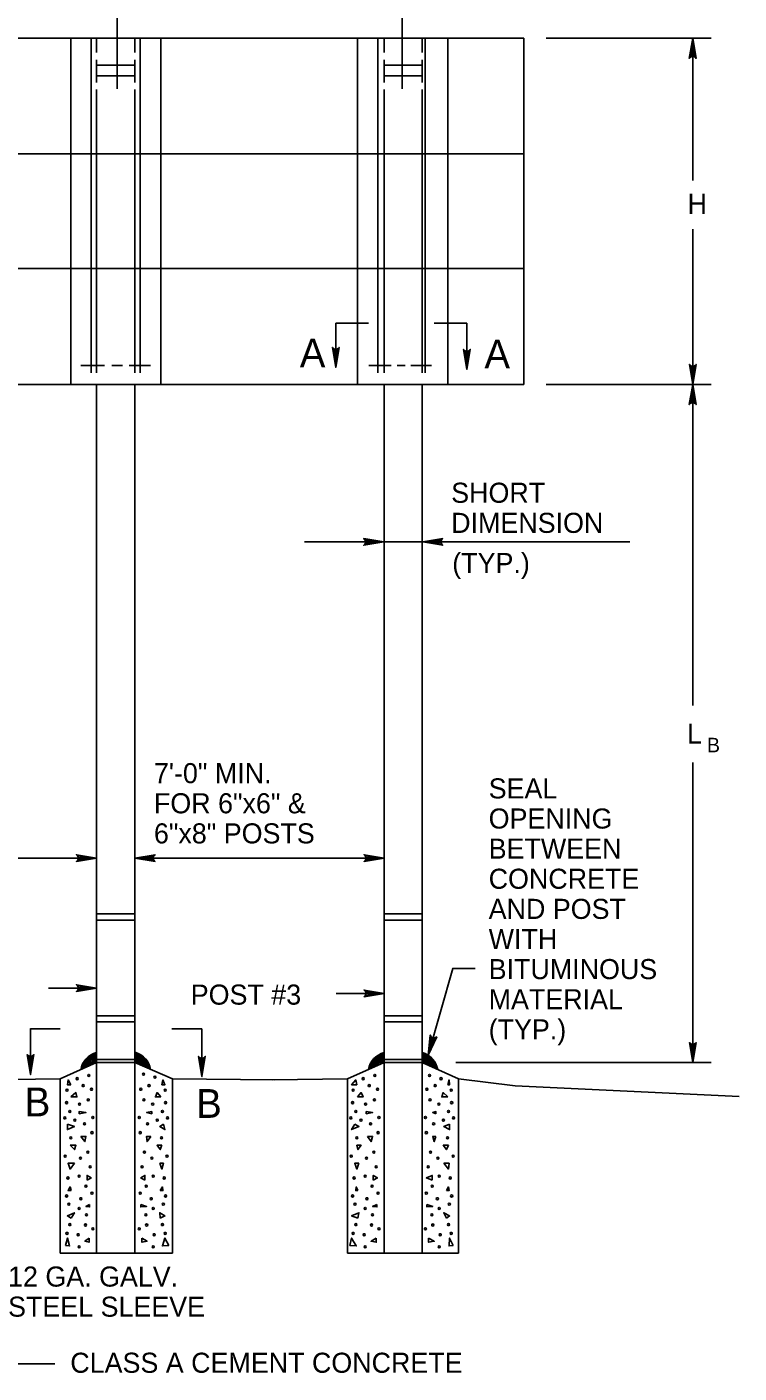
# Model space of a CAD drawing. Extents: x -2340 to 628, y -879 to 309.
# Drawn here: x 247.1 to 353.5, y 1.8 to 203 of the extents above; entities that cross this region are included whole.
import ezdxf

# ---------------------------------------------------------------- set-up
doc = ezdxf.new("R2010")
doc.units = 0
for name, color, linetype in [('Level 2', 7, 'Continuous'), ('Level 3', 7, 'Continuous'), ('Level 4', 7, 'Continuous')]:
    doc.layers.add(name, color=color, linetype=linetype)

# ---------------------------------------------------------------- blocks, each defined once
blk = doc.blocks.new('RARROW')
at = {"layer": 'Level 3'}
blk.add_lwpolyline([(-0.0576, 0.0072), (-0.0555, 0.0031), (0, 0), (-0.0576, 0.0072), (-0.0606, 0.0098), (0, 0), (-0.0555, -0.0027), (-0.0575, -0.0069), (0, 0), (-0.0606, -0.0096), (-0.0575, -0.0069)], dxfattribs=at)

msp = doc.modelspace()

# ---------------------------------------------------------------- linework, layer by layer
at = {"layer": 'Level 2'}
for p, q in [((199.49, 201.26), (321.32, 201.26)), ((253.6, 201.26), (253.6, 149.52)), ((256.67, 201.26), (256.67, 151.25)), ((257.45, 201.26), (257.45, 199.13)), ((263.2, 201.26), (263.2, 199.13)), ((263.99, 201.26), (263.99, 151.25)), ((267.06, 201.26), (267.06, 149.52)), ((296.44, 201.26), (296.44, 149.52)), ((299.51, 201.26), (299.51, 151.25)), ((300.45, 201.26), (300.45, 199.13)), ((306.12, 201.26), (306.12, 199.13)), ((306.59, 201.26), (306.59, 151.25)), ((309.98, 201.26), (309.98, 149.52)), ((321.32, 201.26), (321.32, 149.52)), ((257.45, 198.03), (257.45, 194.65)), ((257.45, 197.24), (263.2, 197.24)), ((263.2, 198.03), (263.2, 194.65)), ((300.45, 198.03), (300.45, 194.65)), ((300.45, 197.24), (306.12, 197.24)), ((306.12, 197.24), (300.45, 197.24)), ((306.12, 198.03), (306.12, 194.65)), ((257.45, 195.67), (263.2, 195.67)), ((300.45, 195.67), (306.12, 195.67)), ((306.12, 195.67), (300.45, 195.67)), ((257.45, 193.62), (257.45, 151.25)), ((263.2, 193.62), (263.2, 151.25)), ((300.45, 193.62), (300.45, 151.25)), ((306.12, 193.62), (306.12, 151.25)), ((199.49, 184.01), (321.32, 184.01)), ((199.49, 166.85), (321.32, 166.85)), ((199.49, 149.52), (321.32, 149.52)), ((257.45, 48.2), (257.45, 149.52)), ((263.2, 48.2), (263.2, 149.52)), ((300.45, 48.2), (300.45, 149.52)), ((306.12, 48.2), (306.12, 149.52)), ((257.45, 70.41), (263.21, 70.41)), ((300.32, 70.41), (306.22, 70.41)), ((300.32, 70.41), (305.99, 70.41)), ((257.45, 69.47), (263.21, 69.47)), ((300.32, 69.47), (306.22, 69.47)), ((300.32, 69.47), (305.99, 69.47)), ((257.45, 55.21), (263.21, 55.21)), ((300.45, 55.21), (306.12, 55.21)), ((257.45, 54.27), (263.21, 54.27)), ((300.45, 54.27), (306.12, 54.27)), ((257.45, 48.68), (263.2, 48.68)), ((300.45, 48.68), (306.12, 48.68)), ((257.45, 48.2), (252.02, 45.76)), ((257.45, 48.2), (263.2, 48.2)), ((257.45, 48.2), (257.45, 19.7)), ((263.2, 48.2), (268.79, 45.76)), ((263.2, 48.2), (263.2, 19.7)), ((300.45, 48.2), (294.94, 45.76)), ((300.45, 48.2), (306.12, 48.2)), ((300.45, 48.2), (300.45, 19.7)), ((306.12, 48.2), (311.56, 45.76)), ((306.12, 48.2), (306.12, 19.7)), ((252.02, 45.76), (252.02, 19.7)), ((268.79, 45.76), (268.79, 19.7)), ((294.94, 45.76), (294.94, 19.7)), ((311.56, 45.76), (311.56, 19.7)), ((252.02, 19.7), (268.79, 19.7)), ((294.94, 19.7), (311.56, 19.7))]:
    msp.add_line(p, q, dxfattribs=at)
for points in [[(252.02, 45.76), (240.92, 45.6)], [(268.79, 45.76), (284.07, 45.6)], [(294.94, 45.76), (283.76, 45.6)], [(311.56, 45.76), (320.02, 44.72), (353.48, 43.14)]]:
    msp.add_lwpolyline(points, dxfattribs=at)
for points in [[(253.6, 44.9), (253.12, 44.9), (253.2, 45.6)], [(267.22, 44.9), (267.69, 44.9), (267.38, 45.6)], [(296.36, 44.9), (295.57, 44.9), (296.2, 45.6)], [(309.98, 44.9), (310.22, 44.9), (310.14, 45.6)], [(253.6, 43.08), (254.54, 43.08), (254.38, 43.71)], [(267.06, 43.08), (266.27, 43.08), (266.51, 43.71)], [(296.44, 43.08), (297.3, 43.08), (296.99, 43.71)], [(309.98, 43.08), (309.04, 43.08), (309.27, 43.71)], [(254.86, 40.56), (254.86, 40.88), (255.88, 40.72)], [(265.72, 40.56), (265.72, 40.88), (264.94, 40.72)], [(297.77, 40.56), (297.77, 40.88), (298.72, 40.72)], [(308.17, 40.56), (308.17, 40.88), (307.7, 40.72)], [(253.12, 38.99), (253.12, 38.2), (254.15, 38.67)], [(267.46, 38.99), (267.69, 38.2), (266.9, 38.67)], [(296.04, 38.99), (295.57, 38.2), (296.67, 38.67)], [(310.22, 38.99), (310.22, 38.2), (309.35, 38.67)], [(255.09, 37.18), (255.88, 37.18), (255.72, 36.39)], [(265.57, 37.18), (264.94, 37.18), (265.01, 36.39)], [(297.93, 37.18), (298.72, 37.18), (298.48, 36.39)], [(308.17, 37.18), (307.7, 37.18), (307.93, 36.39)], [(253.52, 35.84), (254.38, 35.84), (254.15, 35.21)], [(267.22, 35.84), (266.51, 35.84), (266.98, 35.21)], [(296.36, 35.84), (296.99, 35.84), (296.51, 35.21)], [(310.06, 35.84), (309.27, 35.84), (309.74, 35.21)], [(254.15, 33.16), (253.2, 33.16), (253.52, 32.3)], [(266.9, 33.16), (267.46, 33.16), (267.22, 32.3)], [(296.67, 33.16), (296.04, 33.16), (296.36, 32.3)], [(309.35, 33.16), (310.14, 33.16), (310.06, 32.3)], [(256.04, 30.64), (256.04, 31.35), (256.67, 30.96)], [(264.7, 30.64), (264.7, 31.35), (264.07, 30.96)], [(298.8, 30.64), (298.8, 31.35), (299.43, 30.96)], [(307.62, 30.64), (307.62, 31.35), (306.75, 30.96)], [(253.67, 29.07), (253.2, 29.07), (253.52, 29.62)], [(266.98, 29.07), (267.38, 29.07), (267.3, 29.62)], [(296.51, 29.07), (296.2, 29.07), (296.28, 29.62)], [(309.74, 29.07), (310.14, 29.07), (310.06, 29.62)], [(256.43, 27.02), (256.43, 26.63), (255.88, 26.7)], [(264.07, 27.02), (264.07, 26.63), (264.94, 26.7)], [(299.35, 27.02), (299.35, 26.63), (298.72, 26.7)], [(306.83, 27.02), (306.83, 26.63), (307.7, 26.7)], [(253.67, 24.97), (254.15, 25.76), (253.12, 25.29)], [(266.98, 24.97), (266.9, 25.76), (267.69, 25.29)], [(296.51, 24.97), (296.67, 25.76), (295.57, 25.29)], [(309.74, 24.97), (309.35, 25.76), (310.22, 25.29)], [(252.81, 20.88), (253.44, 20.8), (253.12, 21.98)], [(256.35, 21.98), (256.35, 21.35), (255.72, 21.51)], [(264.23, 21.98), (264.23, 21.35), (265.01, 21.51)], [(268.24, 20.88), (267.3, 20.8), (267.69, 21.98)], [(295.33, 20.88), (296.28, 20.8), (295.57, 21.98)], [(299.27, 21.98), (299.27, 21.35), (298.48, 21.51)], [(307.07, 21.98), (307.07, 21.35), (307.93, 21.51)], [(310.77, 20.88), (310.14, 20.8), (310.22, 21.98)]]:
    msp.add_lwpolyline(points, close=True, dxfattribs=at)
for centre, major_axis, start_param, end_param in [((258.64, 46.67), (-3.59, 0), 5.049782, 6.134444), ((258.64, 46.67), (-3.48, 0), 5.061257, 6.112974), ((258.64, 46.67), (-3.35, 0), 5.075898, 6.083179), ((258.64, 46.67), (-3.18, 0), 5.095864, 6.041663), ((258.64, 46.67), (-3.03, 0), 5.116244, 5.998084), ((258.64, 46.67), (-2.87, 0), 5.140569, 5.94416), ((258.64, 46.67), (-2.69, 0), 5.185431, 5.865794), ((258.64, 46.67), (-2.52, 0), 5.215878, 5.780715), ((258.64, 46.67), (-2.35, 0), 5.263543, 5.680676), ((261.99, 46.72), (3.48, 0), 0.164297, 1.213759), ((261.99, 46.72), (2.52, 0), 0.502471, 1.067308), ((261.99, 46.72), (2.69, 0), 0.391681, 1.097754), ((261.99, 46.72), (3.59, 0), 0.143581, 1.218869), ((261.99, 46.72), (3.18, 0), 0.232926, 1.171279), ((261.99, 46.72), (3.03, 0), 0.274712, 1.150118), ((261.99, 46.72), (2.87, 0), 0.326219, 1.124043), ((261.99, 46.72), (2.35, 0), 0.60251, 1.019643), ((261.99, 46.72), (2.17, 0), 0.745101, 0.965881), ((261.99, 46.72), (3.35, 0), 0.193006, 1.190655), ((301.63, 46.68), (-3.59, 0), 5.048279, 6.134323), ((301.63, 46.68), (-3.48, 0), 5.058902, 6.113111), ((301.63, 46.68), (-3.35, 0), 5.073435, 6.083689), ((301.63, 46.68), (-3.18, 0), 5.093253, 6.042722), ((301.63, 46.68), (-3.03, 0), 5.113478, 5.999761), ((301.63, 46.68), (-2.87, 0), 5.137615, 5.946674), ((301.63, 46.68), (-2.69, 0), 5.166915, 5.878941), ((301.63, 46.68), (-2.52, 0), 5.201449, 5.780715), ((301.63, 46.68), (-2.35, 0), 5.238657, 5.680676), ((301.63, 46.68), (-2.17, 0), 5.288522, 5.513079), ((304.89, 46.69), (2.52, 0), 0.502471, 1.067308), ((304.89, 46.69), (2.69, 0), 0.417391, 1.097754), ((304.89, 46.69), (3.59, 0), 0.146911, 1.218869), ((304.89, 46.69), (3.35, 0), 0.197969, 1.190655), ((304.89, 46.69), (3.18, 0), 0.239305, 1.171279), ((304.89, 46.69), (3.03, 0), 0.282682, 1.150118), ((304.89, 46.69), (2.87, 0), 0.336331, 1.124043), ((304.89, 46.69), (2.35, 0), 0.60251, 1.019643), ((304.89, 46.69), (2.17, 0), 0.779924, 0.965881), ((304.89, 46.69), (3.48, 0), 0.168297, 1.204055), ((258.64, 46.67), (-2.17, 0), 5.317304, 5.495478)]:
    msp.add_ellipse(centre, major_axis=major_axis, ratio=0.9, start_param=start_param, end_param=end_param, dxfattribs=at)
for centre, major_axis, ratio in [((256.3, 46.28), (0.154, 0), 0.99999), ((264.47, 46.46), (-0.154, 0), 0.9), ((299.04, 46.28), (0.154, 0), 0.99999), ((307.22, 46.28), (-0.154, 0), 0.99999), ((254.57, 45.8), (0.154, 0), 0.99999), ((255.47, 44.76), (0.154, 0), 0.99999), ((256.71, 44.21), (0.154, 0), 0.99999), ((264.06, 44.21), (-0.154, 0), 0.99999), ((265.3, 44.76), (-0.154, 0), 0.99999), ((266.19, 46.03), (-0.154, 0), 0.9), ((297.32, 45.8), (0.154, 0), 0.99999), ((298.22, 44.76), (0.154, 0), 0.99999), ((299.46, 44.21), (0.154, 0), 0.99999), ((306.81, 44.21), (-0.154, 0), 0.99999), ((308.05, 44.76), (-0.154, 0), 0.99999), ((308.94, 45.8), (-0.154, 0), 0.99999), ((252.99, 42.21), (0.154, 0), 0.99999), ((253.05, 44.07), (0.154, 0), 0.99999), ((256.23, 42.62), (0.154, 0), 0.99999), ((264.54, 42.62), (-0.154, 0), 0.99999), ((267.71, 44.07), (-0.154, 0), 0.99999), ((267.78, 42.21), (-0.154, 0), 0.99999), ((295.73, 42.21), (0.154, 0), 0.99999), ((295.8, 44.07), (0.154, 0), 0.99999), ((298.98, 42.62), (0.154, 0), 0.99999), ((307.29, 42.62), (-0.154, 0), 0.99999), ((310.46, 44.07), (-0.154, 0), 0.99999), ((310.53, 42.21), (-0.154, 0), 0.99999), ((253.47, 40.9), (0.154, 0), 0.99999), ((254.92, 42), (0.154, 0), 0.99999), ((265.85, 42), (-0.154, 0), 0.99999), ((267.3, 40.9), (-0.154, 0), 0.99999), ((296.22, 40.9), (0.154, 0), 0.99999), ((297.67, 42), (0.154, 0), 0.99999), ((308.6, 42), (-0.154, 0), 0.99999), ((310.05, 40.9), (-0.154, 0), 0.99999), ((252.71, 39.93), (0.154, 0), 0.99999), ((254.23, 39.59), (0.154, 0), 0.99999), ((255.67, 39.04), (0.154, 0), 0.99999), ((256.92, 40), (0.154, 0), 0.99999), ((263.85, 40), (-0.154, 0), 0.99999), ((265.09, 39.04), (-0.154, 0), 0.99999), ((266.54, 39.59), (-0.154, 0), 0.99999), ((268.06, 39.93), (-0.154, 0), 0.99999), ((295.46, 39.93), (0.154, 0), 0.99999), ((296.98, 39.59), (0.154, 0), 0.99999), ((298.42, 39.04), (0.154, 0), 0.99999), ((299.67, 40), (0.154, 0), 0.99999), ((306.6, 40), (-0.154, 0), 0.99999), ((307.84, 39.04), (-0.154, 0), 0.99999), ((309.29, 39.59), (-0.154, 0), 0.99999), ((310.81, 39.93), (-0.154, 0), 0.99999), ((253.61, 36.97), (0.154, 0), 0.99999), ((256.78, 37.73), (0.154, 0), 0.99999), ((263.99, 37.73), (-0.154, 0), 0.99999), ((267.16, 36.97), (-0.154, 0), 0.99999), ((296.36, 36.97), (0.154, 0), 0.99999), ((299.53, 37.73), (0.154, 0), 0.99999), ((306.74, 37.73), (-0.154, 0), 0.99999), ((309.91, 36.97), (-0.154, 0), 0.99999), ((252.78, 34.21), (0.154, 0), 0.99999), ((256.16, 34.83), (0.154, 0), 0.99999), ((264.61, 34.83), (-0.154, 0), 0.99999), ((267.99, 34.21), (-0.154, 0), 0.99999), ((295.53, 34.21), (0.154, 0), 0.99999), ((298.91, 34.83), (0.154, 0), 0.99999), ((307.36, 34.83), (-0.154, 0), 0.99999), ((310.74, 34.21), (-0.154, 0), 0.99999), ((255.05, 33.93), (0.154, 0), 0.99999), ((256.5, 32.62), (0.154, 0), 0.99999), ((264.26, 32.62), (-0.154, 0), 0.99999), ((265.71, 33.93), (-0.154, 0), 0.99999), ((297.8, 33.93), (0.154, 0), 0.99999), ((299.25, 32.62), (0.154, 0), 0.99999), ((307.01, 32.62), (-0.154, 0), 0.99999), ((308.46, 33.93), (-0.154, 0), 0.99999), ((253.19, 30.96), (0.154, 0), 0.99999), ((254.85, 31.24), (0.154, 0), 0.99999), ((265.92, 31.24), (-0.154, 0), 0.99999), ((267.57, 30.96), (-0.154, 0), 0.99999), ((295.94, 30.96), (0.154, 0), 0.99999), ((297.6, 31.24), (0.154, 0), 0.99999), ((308.67, 31.24), (-0.154, 0), 0.99999), ((310.32, 30.96), (-0.154, 0), 0.99999), ((252.99, 28.27), (0.154, 0), 0.99999), ((255.88, 29.72), (0.154, 0), 0.99999), ((256.78, 28.69), (0.154, 0), 0.99999), ((263.99, 28.69), (-0.154, 0), 0.99999), ((264.88, 29.72), (-0.154, 0), 0.99999), ((267.78, 28.27), (-0.154, 0), 0.99999), ((295.73, 28.27), (0.154, 0), 0.99999), ((298.63, 29.72), (0.154, 0), 0.99999), ((299.53, 28.69), (0.154, 0), 0.99999), ((306.74, 28.69), (-0.154, 0), 0.99999), ((307.63, 29.72), (-0.154, 0), 0.99999), ((310.53, 28.27), (-0.154, 0), 0.99999), ((253.33, 27.03), (0.154, 0), 0.99999), ((254.85, 26.41), (0.154, 0), 0.99999), ((255.12, 27.86), (0.154, 0), 0.99999), ((265.64, 27.86), (-0.154, 0), 0.99999), ((265.92, 26.41), (-0.154, 0), 0.99999), ((267.44, 27.03), (-0.154, 0), 0.99999), ((296.08, 27.03), (0.154, 0), 0.99999), ((297.6, 26.41), (0.154, 0), 0.99999), ((297.87, 27.86), (0.154, 0), 0.99999), ((308.39, 27.86), (-0.154, 0), 0.99999), ((308.67, 26.41), (-0.154, 0), 0.99999), ((310.18, 27.03), (-0.154, 0), 0.99999), ((253.47, 23.99), (0.154, 0), 0.99999), ((255.95, 25.44), (0.154, 0), 0.99999), ((264.82, 25.44), (-0.154, 0), 0.99999), ((267.3, 23.99), (-0.154, 0), 0.99999), ((296.22, 23.99), (0.154, 0), 0.99999), ((298.7, 25.44), (0.154, 0), 0.99999), ((307.56, 25.44), (-0.154, 0), 0.99999), ((310.05, 23.99), (-0.154, 0), 0.99999), ((253.05, 22.68), (0.154, 0), 0.99999), ((254.71, 22.48), (0.154, 0), 0.99999), ((255.81, 23.93), (0.154, 0), 0.99999), ((256.92, 23.37), (0.154, 0), 0.99999), ((263.85, 23.37), (-0.154, 0), 0.99999), ((264.95, 23.93), (-0.154, 0), 0.99999), ((266.06, 22.48), (-0.154, 0), 0.99999), ((267.71, 22.68), (-0.154, 0), 0.99999), ((295.8, 22.68), (0.154, 0), 0.99999), ((297.46, 22.48), (0.154, 0), 0.99999), ((298.56, 23.93), (0.154, 0), 0.99999), ((299.67, 23.37), (0.154, 0), 0.99999), ((306.6, 23.37), (-0.154, 0), 0.99999), ((307.7, 23.93), (-0.154, 0), 0.99999), ((308.81, 22.48), (-0.154, 0), 0.99999), ((310.46, 22.68), (-0.154, 0), 0.99999), ((254.85, 20.68), (0.154, 0), 0.99999), ((265.92, 20.68), (-0.154, 0), 0.99999), ((297.6, 20.68), (0.154, 0), 0.99999), ((308.67, 20.68), (-0.154, 0), 0.99999)]:
    msp.add_ellipse(centre, major_axis=major_axis, ratio=ratio, dxfattribs=at)
at = {"layer": 'Level 3'}
for p, q in [((260.53, 209.77), (260.53, 193.7)), ((303.13, 209.77), (303.13, 193.7)), ((324.63, 201.26), (349.31, 201.26)), ((346.55, 180.01), (346.55, 201.26)), ((346.55, 149.52), (346.55, 172.75)), ((293.2, 158.67), (293.2, 152.07)), ((298.08, 158.67), (293.2, 158.67)), ((312.81, 158.67), (307.93, 158.67)), ((312.81, 158.67), (312.81, 151.77)), ((258.63, 152.37), (255.12, 152.37)), ((261.32, 152.37), (259.76, 152.37)), ((265.51, 152.37), (262.32, 152.37)), ((301.47, 152.37), (298.15, 152.37)), ((303.6, 152.37), (302.41, 152.37)), ((307.53, 152.37), (304.42, 152.37)), ((324.63, 149.52), (349.31, 149.52)), ((346.55, 101.57), (346.55, 149.52)), ((288.54, 126), (306.12, 126)), ((306.2, 126), (337.14, 126)), ((346.55, 48.2), (346.55, 93.04)), ((257.45, 78.76), (220.6, 78.76)), ((300.45, 78.76), (263.2, 78.76)), ((250.26, 59.33), (257.45, 59.33)), ((293.29, 58.54), (300.45, 58.54)), ((247.61, 46.4), (247.61, 53.28)), ((252.02, 53.24), (247.61, 53.24)), ((268.72, 53.24), (273.2, 53.24)), ((273.2, 53.24), (273.2, 46.12)), ((349.31, 48.2), (311.16, 48.2)), ((243.35, 3.18), (251.23, 3.18))]:
    msp.add_line(p, q, dxfattribs=at)
msp.add_lwpolyline([(307.01, 49.29), (310.68, 62.26), (314.04, 62.26)], dxfattribs=at)

# ---------------------------------------------------------------- block references
at = {"layer": 'Level 2'}
for p, xscale, yscale, rotation in [((346.55, 201.26), 49.50530586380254, 51.54709073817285, 89.99999999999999), ((293.2, 152.07), 49.50530586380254, 51.54709073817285, -90.00000000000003), ((312.81, 151.77), 49.50530586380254, 51.54709073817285, -90.00000000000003), ((346.55, 149.52), 49.50530586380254, 51.54709073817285, -90.00000000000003), ((346.55, 149.52), 49.50530586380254, 51.54709073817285, 89.99999999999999), ((306.2, 126), 49.50530586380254, 51.54709073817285, 180), ((263.2, 78.76), 49.50530586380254, 51.54709073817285, 180), ((307.01, 49.29), 49.50530586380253, 51.547090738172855, -105.57754519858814), ((346.55, 48.2), 49.50530586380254, 51.54709073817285, -90.00000000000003), ((247.61, 46.4), 49.50530586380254, 51.54709073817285, -90.00000000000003), ((273.2, 46.12), 49.50530586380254, 51.54709073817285, -90.00000000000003)]:
    msp.add_blockref('RARROW', p, dxfattribs=dict(at, xscale=xscale, yscale=yscale, rotation=rotation))
at = {"layer": 'Level 2', "xscale": 49.50530586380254, "yscale": 51.54709073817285}
for p in [(300.38, 126), (257.45, 78.76), (300.45, 78.76), (257.45, 59.33), (300.45, 58.54)]:
    msp.add_blockref('RARROW', p, dxfattribs=at)

# ---------------------------------------------------------------- texts
at = {"layer": 'Level 2'}
for s, p in [('7\'-0" MIN.', (266.04, 89.95)), ('FOR 6"x6" &', (266.04, 85.45)), ('6"x8" POSTS', (266.04, 80.95))]:
    msp.add_text(s, height=3, dxfattribs=at).set_placement(p)
at = {"layer": 'Level 3'}
for s, height, p in [('H', 3, (345.79, 175.02)), ('A', 4.3, (287.83, 152.08)), ('A', 4.3, (315.42, 151.92)), ('SHORT', 3, (310.46, 131.85)), ('DIMENSION', 3, (310.46, 127.35)), ('(TYP.)', 3, (310.62, 121.35)), ('L', 3, (345.7, 95.86)), ('SEAL', 3, (316.06, 87.67)), ('OPENING ', 3, (316.06, 83.17)), ('BETWEEN', 3, (316.06, 78.67)), ('CONCRETE', 3, (316.06, 74.17)), ('AND POST', 3, (316.06, 69.67)), ('WITH', 3, (316.06, 65.17)), ('BITUMINOUS ', 3, (316.06, 60.67)), ('POST #3', 3, (271.54, 56.86)), ('MATERIAL', 3, (316.06, 56.17)), ('(TYP.)', 3, (316.06, 51.67)), ('B', 4.3, (246.72, 40.17)), ('B', 4.3, (272.34, 39.94)), ('12 GA. GALV.', 3, (244.24, 14.73)), ('STEEL SLEEVE', 3, (244.24, 10.23)), ('CLASS A CEMENT CONCRETE ', 3, (253.54, 1.85))]:
    msp.add_text(s, height=height, dxfattribs=at).set_placement(p)
at = {"layer": 'Level 4'}
msp.add_text('B', height=2.16, dxfattribs=at).set_placement((348.7, 94.57))

doc.saveas('drawing.dxf')
